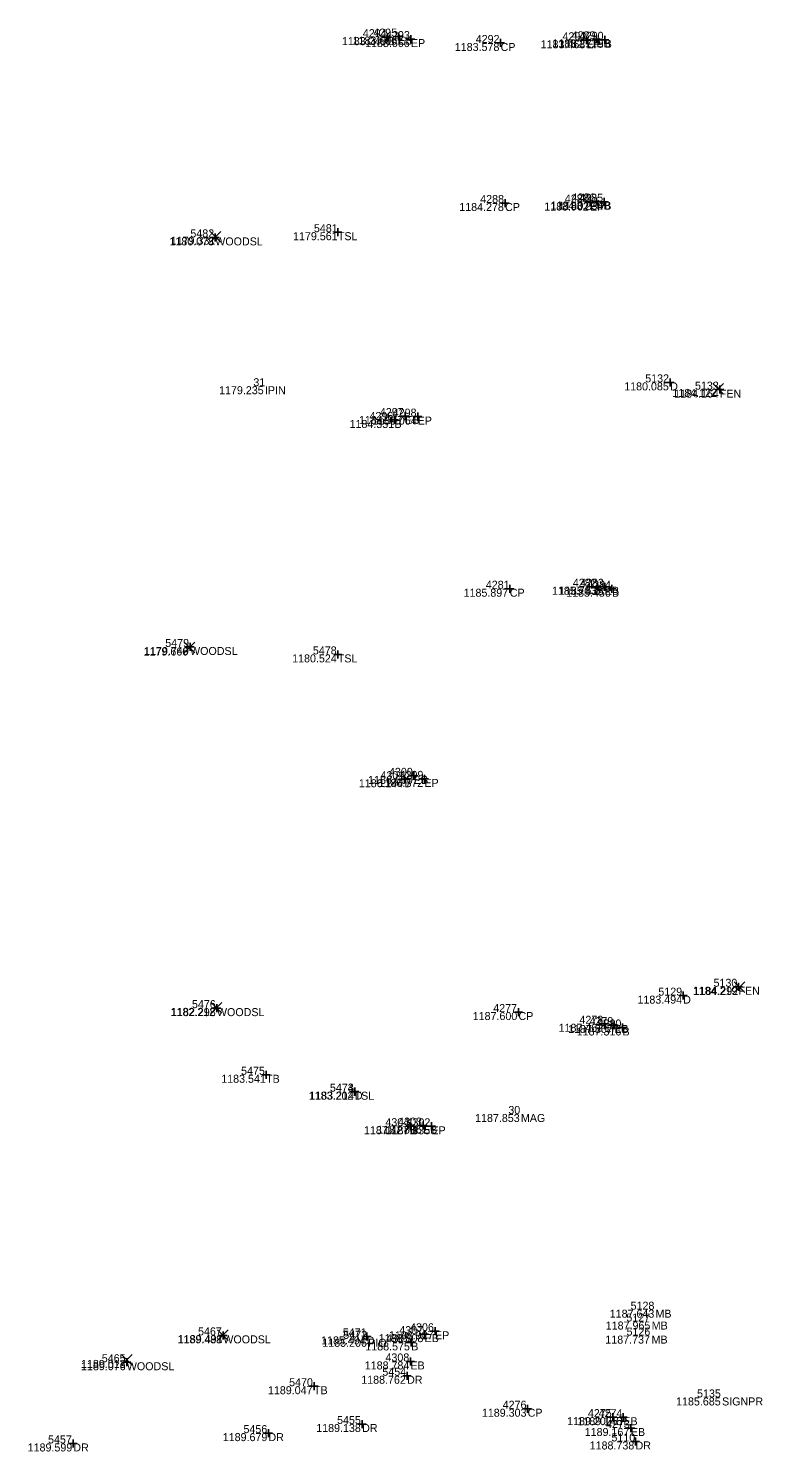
# Model space of a CAD drawing. Extents: x 2044997 to 2050342, y 455233 to 458054.
# Drawn here: x 2047553.1 to 2047644.9, y 457876.5 to 458054.4 of the extents above; entities that cross this region are included whole.
import ezdxf

# ---------------------------------------------------------------- set-up
doc = ezdxf.new("R2010")
doc.units = 0
for name, color, linetype in [('SV_X_Random_Point', 7, 'Continuous'), ('SV_X_Shot_Marker', 7, 'Continuous'), ('SV_X_Text_Comment', 7, 'Continuous'), ('SV_X_Text_Elevation', 7, 'Continuous'), ('SV_X_Text_Name', 7, 'Continuous')]:
    doc.layers.add(name, color=color, linetype=linetype)

msp = doc.modelspace()

# ---------------------------------------------------------------- linework, layer by layer
at = {"layer": 'SV_X_Random_Point'}
for p, q in [((2047575.85, 458027.66), (2047577.18, 458028.99)), ((2047575.85, 458028.99), (2047577.18, 458027.66)), ((2047638.7, 458008.64), (2047640.03, 458009.97)), ((2047638.7, 458009.97), (2047640.03, 458008.64)), ((2047572.58, 457976.32), (2047573.91, 457977.65)), ((2047572.58, 457977.65), (2047573.91, 457976.32)), ((2047641.36, 457933.88), (2047642.69, 457935.21)), ((2047641.36, 457935.21), (2047642.69, 457933.88)), ((2047575.95, 457931.27), (2047577.29, 457932.61)), ((2047575.95, 457932.61), (2047577.29, 457931.27)), ((2047576.74, 457890.38), (2047578.08, 457891.72)), ((2047576.74, 457891.72), (2047578.08, 457890.38)), ((2047564.73, 457887.27), (2047566.07, 457888.61)), ((2047564.73, 457888.61), (2047566.07, 457887.27))]:
    msp.add_line(p, q, dxfattribs=at)
at = {"layer": 'SV_X_Shot_Marker'}
for p, q in [((2047597.52, 458053.27), (2047598.52, 458053.27)), ((2047598.02, 458053.77), (2047598.02, 458052.77)), ((2047598.02, 458053.27), (2047598.02, 458053.27)), ((2047598.87, 458053.34), (2047599.87, 458053.34)), ((2047599.37, 458053.84), (2047599.37, 458052.84)), ((2047599.37, 458053.34), (2047599.37, 458053.34)), ((2047600.44, 458053.03), (2047601.44, 458053.03)), ((2047600.94, 458053.53), (2047600.94, 458052.53)), ((2047600.94, 458053.03), (2047600.94, 458053.03)), ((2047611.66, 458052.54), (2047612.66, 458052.54)), ((2047612.16, 458053.04), (2047612.16, 458052.04)), ((2047612.16, 458052.54), (2047612.16, 458052.54)), ((2047622.4, 458052.88), (2047623.4, 458052.88)), ((2047622.9, 458053.38), (2047622.9, 458052.38)), ((2047622.9, 458052.88), (2047622.9, 458052.88)), ((2047623.65, 458053), (2047624.65, 458053)), ((2047624.15, 458053.5), (2047624.15, 458052.5)), ((2047624.15, 458053), (2047624.15, 458053)), ((2047624.68, 458052.94), (2047625.68, 458052.94)), ((2047625.18, 458053.44), (2047625.18, 458052.44)), ((2047625.18, 458052.94), (2047625.18, 458052.94)), ((2047612.72, 458033.04), (2047612.72, 458032.04)), ((2047623.35, 458033.1), (2047623.35, 458032.1)), ((2047624.15, 458033.23), (2047624.15, 458032.23)), ((2047625.13, 458033.2), (2047625.13, 458032.2)), ((2047612.22, 458032.54), (2047613.22, 458032.54)), ((2047612.72, 458032.54), (2047612.72, 458032.54)), ((2047622.85, 458032.6), (2047623.85, 458032.6)), ((2047623.35, 458032.6), (2047623.35, 458032.6)), ((2047623.65, 458032.73), (2047624.65, 458032.73)), ((2047624.15, 458032.73), (2047624.15, 458032.73)), ((2047624.63, 458032.7), (2047625.63, 458032.7)), ((2047625.13, 458032.7), (2047625.13, 458032.7)), ((2047591.81, 458029.39), (2047591.81, 458028.39)), ((2047575.97, 458028.24), (2047576.97, 458028.24)), ((2047576.47, 458028.74), (2047576.47, 458027.74)), ((2047576.47, 458028.24), (2047576.47, 458028.24)), ((2047591.31, 458028.89), (2047592.31, 458028.89)), ((2047591.81, 458028.89), (2047591.81, 458028.89)), ((2047632.87, 458010.12), (2047633.87, 458010.12)), ((2047633.37, 458010.62), (2047633.37, 458009.62)), ((2047633.37, 458010.12), (2047633.37, 458010.12)), ((2047639.58, 458009.71), (2047639.58, 458008.71)), ((2047639.08, 458009.21), (2047640.08, 458009.21)), ((2047639.58, 458009.21), (2047639.58, 458009.21)), ((2047600.22, 458006.41), (2047600.22, 458005.41)), ((2047601.79, 458006.34), (2047601.79, 458005.34)), ((2047598.38, 458005.42), (2047599.38, 458005.42)), ((2047598.88, 458005.92), (2047598.88, 458004.92)), ((2047598.88, 458005.42), (2047598.88, 458005.42)), ((2047599.72, 458005.91), (2047600.72, 458005.91)), ((2047600.22, 458005.91), (2047600.22, 458005.91)), ((2047601.29, 458005.84), (2047602.29, 458005.84)), ((2047601.79, 458005.84), (2047601.79, 458005.84)), ((2047613.31, 457984.83), (2047613.31, 457983.83)), ((2047624.3, 457985.08), (2047624.3, 457984.08)), ((2047625.21, 457985.07), (2047625.21, 457984.07)), ((2047626.09, 457984.83), (2047626.09, 457983.83)), ((2047612.81, 457984.33), (2047613.81, 457984.33)), ((2047613.31, 457984.33), (2047613.31, 457984.33)), ((2047623.8, 457984.58), (2047624.8, 457984.58)), ((2047624.3, 457984.58), (2047624.3, 457984.58)), ((2047624.71, 457984.57), (2047625.71, 457984.57)), ((2047625.21, 457984.57), (2047625.21, 457984.57)), ((2047625.59, 457984.33), (2047626.59, 457984.33)), ((2047626.09, 457984.33), (2047626.09, 457984.33)), ((2047572.82, 457977.05), (2047573.82, 457977.05)), ((2047573.32, 457977.55), (2047573.32, 457976.55)), ((2047573.32, 457977.05), (2047573.32, 457977.05)), ((2047591.3, 457976.12), (2047592.3, 457976.12)), ((2047591.8, 457976.62), (2047591.8, 457975.62)), ((2047591.8, 457976.12), (2047591.8, 457976.12)), ((2047599.63, 457960.52), (2047600.63, 457960.52)), ((2047600.13, 457961.02), (2047600.13, 457960.02)), ((2047600.13, 457960.52), (2047600.13, 457960.52)), ((2047600.82, 457960.94), (2047601.82, 457960.94)), ((2047601.32, 457961.44), (2047601.32, 457960.44)), ((2047601.32, 457960.94), (2047601.32, 457960.94)), ((2047602.13, 457960.56), (2047603.13, 457960.56)), ((2047602.63, 457961.06), (2047602.63, 457960.06)), ((2047602.63, 457960.56), (2047602.63, 457960.56)), ((2047641.91, 457935.08), (2047641.91, 457934.08)), ((2047634.49, 457933.47), (2047635.49, 457933.47)), ((2047634.99, 457933.97), (2047634.99, 457932.97)), ((2047634.99, 457933.47), (2047634.99, 457933.47)), ((2047641.41, 457934.58), (2047642.41, 457934.58)), ((2047641.91, 457934.58), (2047641.91, 457934.58)), ((2047576.18, 457931.91), (2047577.18, 457931.91)), ((2047576.68, 457932.41), (2047576.68, 457931.41)), ((2047576.68, 457931.91), (2047576.68, 457931.91)), ((2047613.9, 457931.42), (2047614.9, 457931.42)), ((2047614.4, 457931.92), (2047614.4, 457930.92)), ((2047614.4, 457931.42), (2047614.4, 457931.42)), ((2047624.64, 457929.95), (2047625.64, 457929.95)), ((2047625.14, 457930.45), (2047625.14, 457929.45)), ((2047625.14, 457929.95), (2047625.14, 457929.95)), ((2047625.88, 457929.8), (2047626.88, 457929.8)), ((2047626.38, 457930.3), (2047626.38, 457929.3)), ((2047626.38, 457929.8), (2047626.38, 457929.8)), ((2047627.41, 457929.99), (2047627.41, 457928.99)), ((2047626.91, 457929.49), (2047627.91, 457929.49)), ((2047627.41, 457929.49), (2047627.41, 457929.49)), ((2047582.33, 457923.58), (2047583.33, 457923.58)), ((2047582.83, 457924.08), (2047582.83, 457923.08)), ((2047582.83, 457923.58), (2047582.83, 457923.58)), ((2047593.4, 457921.46), (2047594.4, 457921.46)), ((2047593.43, 457921.48), (2047594.43, 457921.48)), ((2047593.9, 457921.96), (2047593.9, 457920.96)), ((2047593.9, 457921.46), (2047593.9, 457921.46)), ((2047593.93, 457921.98), (2047593.93, 457920.98)), ((2047593.93, 457921.48), (2047593.93, 457921.48)), ((2047600.34, 457917.15), (2047601.34, 457917.15)), ((2047600.84, 457917.65), (2047600.84, 457916.65)), ((2047600.84, 457917.15), (2047600.84, 457917.15)), ((2047601.96, 457917.23), (2047602.96, 457917.23)), ((2047602.46, 457917.73), (2047602.46, 457916.73)), ((2047602.46, 457917.23), (2047602.46, 457917.23)), ((2047603.01, 457917.14), (2047604.01, 457917.14)), ((2047603.51, 457917.64), (2047603.51, 457916.64)), ((2047603.51, 457917.14), (2047603.51, 457917.14)), ((2047576.98, 457891.01), (2047577.98, 457891.01)), ((2047577.48, 457891.51), (2047577.48, 457890.51)), ((2047577.48, 457891.01), (2047577.48, 457891.01)), ((2047594.91, 457890.88), (2047595.91, 457890.88)), ((2047595.41, 457891.38), (2047595.41, 457890.38)), ((2047595.41, 457890.88), (2047595.41, 457890.88)), ((2047600.98, 457890.63), (2047600.98, 457889.63)), ((2047602.15, 457891.16), (2047603.15, 457891.16)), ((2047602.65, 457891.66), (2047602.65, 457890.66)), ((2047602.65, 457891.16), (2047602.65, 457891.16)), ((2047603.46, 457891.52), (2047604.46, 457891.52)), ((2047603.96, 457892.02), (2047603.96, 457891.02)), ((2047603.96, 457891.52), (2047603.96, 457891.52)), ((2047600.48, 457890.13), (2047601.48, 457890.13)), ((2047600.98, 457890.13), (2047600.98, 457890.13)), ((2047564.91, 457887.65), (2047565.91, 457887.65)), ((2047565.41, 457888.15), (2047565.41, 457887.15)), ((2047565.41, 457887.65), (2047565.41, 457887.65)), ((2047600.38, 457887.75), (2047601.38, 457887.75)), ((2047600.88, 457888.25), (2047600.88, 457887.25)), ((2047600.88, 457887.75), (2047600.88, 457887.75)), ((2047588.83, 457885.15), (2047588.83, 457884.15)), ((2047599.96, 457885.96), (2047600.96, 457885.96)), ((2047600.46, 457886.46), (2047600.46, 457885.46)), ((2047600.46, 457885.96), (2047600.46, 457885.96)), ((2047588.33, 457884.65), (2047589.33, 457884.65)), ((2047588.83, 457884.65), (2047588.83, 457884.65)), ((2047615.04, 457881.84), (2047616.04, 457881.84)), ((2047615.54, 457882.34), (2047615.54, 457881.34)), ((2047615.54, 457881.84), (2047615.54, 457881.84)), ((2047594.34, 457879.93), (2047595.34, 457879.93)), ((2047594.84, 457880.43), (2047594.84, 457879.43)), ((2047594.84, 457879.93), (2047594.84, 457879.93)), ((2047625.71, 457880.79), (2047626.71, 457880.79)), ((2047626.21, 457881.29), (2047626.21, 457880.29)), ((2047626.21, 457880.79), (2047626.21, 457880.79)), ((2047627.01, 457880.78), (2047628.01, 457880.78)), ((2047627.51, 457881.28), (2047627.51, 457880.28)), ((2047627.51, 457880.78), (2047627.51, 457880.78)), ((2047628.45, 457879.93), (2047628.45, 457878.93)), ((2047558.72, 457878), (2047558.72, 457877)), ((2047582.62, 457878.79), (2047583.62, 457878.79)), ((2047583.12, 457879.29), (2047583.12, 457878.29)), ((2047583.12, 457878.79), (2047583.12, 457878.79)), ((2047627.95, 457879.43), (2047628.95, 457879.43)), ((2047628.45, 457879.43), (2047628.45, 457879.43)), ((2047629.04, 457878.25), (2047629.04, 457877.25)), ((2047558.22, 457877.5), (2047559.22, 457877.5)), ((2047558.72, 457877.5), (2047558.72, 457877.5)), ((2047628.54, 457877.75), (2047629.54, 457877.75)), ((2047629.04, 457877.75), (2047629.04, 457877.75))]:
    msp.add_line(p, q, dxfattribs=at)

# ---------------------------------------------------------------- texts
at = {"layer": 'SV_X_Text_Comment'}
for s, p in [('B', (2047598.02, 458052.27)), ('EB', (2047599.37, 458052.34)), ('EP', (2047600.94, 458052.03)), ('CP', (2047612.16, 458051.54)), ('EP', (2047622.9, 458051.88)), ('EB', (2047624.15, 458052)), ('B', (2047625.18, 458051.94)), ('CP', (2047612.72, 458031.54)), ('EP', (2047623.35, 458031.6)), ('EB', (2047624.15, 458031.73)), ('B', (2047625.13, 458031.7)), ('WOODSL', (2047576.47, 458027.24)), ('TSL', (2047591.81, 458027.89)), ('IPIN', (2047582.69, 458008.64)), ('D', (2047633.37, 458009.12)), ('FEN', (2047639.58, 458008.21)), ('B', (2047598.88, 458004.42)), ('EB', (2047600.22, 458004.91)), ('EP', (2047601.79, 458004.84)), ('CP', (2047613.31, 457983.33)), ('EP', (2047624.3, 457983.58)), ('EB', (2047625.21, 457983.57)), ('B', (2047626.09, 457983.33)), ('WOODSL', (2047573.32, 457976.05)), ('TSL', (2047591.8, 457975.12)), ('B', (2047600.13, 457959.52)), ('EB', (2047601.32, 457959.94)), ('EP', (2047602.63, 457959.56)), ('D', (2047634.99, 457932.47)), ('FEN', (2047641.91, 457933.58)), ('WOODSL', (2047576.68, 457930.91)), ('CP', (2047614.4, 457930.42)), ('EP', (2047625.14, 457928.95)), ('EB', (2047626.38, 457928.8)), ('B', (2047627.41, 457928.49)), ('TB', (2047582.83, 457922.58)), ('TSL', (2047593.9, 457920.46)), ('D', (2047593.93, 457920.48)), ('B', (2047600.84, 457916.15)), ('EB', (2047602.46, 457916.23)), ('EP', (2047603.51, 457916.14)), ('MAG', (2047614.7, 457917.68)), ('MB', (2047631.53, 457893.22)), ('MB', (2047631.06, 457891.74)), ('WOODSL', (2047577.48, 457890.01)), ('D', (2047595.41, 457889.88)), ('PIO', (2047595.6, 457889.58)), ('EB', (2047602.65, 457890.16)), ('EP', (2047603.96, 457890.52)), ('MB', (2047631.04, 457889.98)), ('B', (2047600.98, 457889.13)), ('WOODSL', (2047565.41, 457886.65)), ('EB', (2047600.88, 457886.75)), ('DR', (2047600.46, 457884.96)), ('TB', (2047588.83, 457883.65)), ('CP', (2047615.54, 457880.84)), ('SIGNPR', (2047639.86, 457882.25)), ('DR', (2047594.84, 457878.93)), ('EP', (2047626.21, 457879.79)), ('EB', (2047627.51, 457879.78)), ('DR', (2047583.12, 457877.79)), ('EB', (2047628.45, 457878.43)), ('DR', (2047558.72, 457876.5)), ('DR', (2047629.04, 457876.75))]:
    msp.add_text(s, height=1, dxfattribs=at).set_placement(p)
at = {"layer": 'SV_X_Text_Elevation'}
for s, p in [('1183.249', (2047592.31, 458052.27)), ('1183.606', (2047593.64, 458052.34)), ('1183.666', (2047595.21, 458052.03)), ('1183.578', (2047606.43, 458051.54)), ('1183.463', (2047617.17, 458051.88)), ('1183.211', (2047618.64, 458052)), ('1182.779', (2047619.47, 458051.94)), ('1184.072', (2047618.42, 458031.73)), ('1184.278', (2047606.99, 458031.54)), ('1183.902', (2047617.62, 458031.6)), ('1183.234', (2047619.43, 458031.7)), ('1180.078', (2047570.74, 458027.24)), ('1179.331', (2047570.9, 458027.33)), ('1179.561', (2047586.2, 458027.89)), ('1179.235', (2047576.95, 458008.64)), ('1180.085', (2047627.62, 458009.12)), ('1184.122', (2047633.64, 458008.3)), ('1184.164', (2047633.87, 458008.21)), ('1184.551', (2047593.27, 458004.42)), ('1184.947', (2047594.44, 458004.91)), ('1185.064', (2047596.08, 458004.84)), ('1185.897', (2047607.53, 457983.33)), ('1185.733', (2047618.58, 457983.58)), ('1185.635', (2047619.46, 457983.57)), ('1185.456', (2047620.36, 457983.33)), ('1179.666', (2047567.51, 457975.98)), ('1179.740', (2047567.58, 457976.05)), ('1180.524', (2047586.09, 457975.12)), ('1186.144', (2047594.43, 457959.52)), ('1186.600', (2047595.59, 457959.94)), ('1186.772', (2047596.9, 457959.56)), ('1183.494', (2047629.28, 457932.47)), ('1184.219', (2047636.2, 457933.58)), ('1184.292', (2047636.29, 457933.55)), ('1182.212', (2047570.89, 457930.94)), ('1182.298', (2047570.95, 457930.91)), ('1187.600', (2047608.67, 457930.42)), ('1187.462', (2047619.41, 457928.95)), ('1187.367', (2047620.6, 457928.8)), ('1187.316', (2047621.68, 457928.49)), ('1183.541', (2047577.22, 457922.58)), ('1183.202', (2047588.17, 457920.46)), ('1183.214', (2047588.23, 457920.48)), ('1187.427', (2047595.07, 457916.15)), ('1187.886', (2047596.72, 457916.23)), ('1187.835', (2047597.77, 457916.14)), ('1187.853', (2047608.97, 457917.68)), ('1187.643', (2047625.81, 457893.22)), ('1187.965', (2047625.31, 457891.74)), ('1189.488', (2047571.75, 457890.01)), ('1189.491', (2047571.8, 457890.05)), ('1185.494', (2047589.71, 457889.88)), ('1185.206', (2047589.86, 457889.58)), ('1188.808', (2047596.92, 457890.16)), ('1188.927', (2047598.19, 457890.52)), ('1187.737', (2047625.26, 457889.98)), ('1188.575', (2047595.24, 457889.13)), ('1189.013', (2047559.68, 457886.94)), ('1189.076', (2047559.68, 457886.65)), ('1188.784', (2047595.17, 457886.75)), ('1188.762', (2047594.73, 457884.96)), ('1189.047', (2047583.06, 457883.65)), ('1189.303', (2047609.82, 457880.84)), ('1185.685', (2047634.11, 457882.25)), ('1189.138', (2047589.1, 457878.93)), ('1189.200', (2047620.48, 457879.79)), ('1189.146', (2047621.77, 457879.78)), ('1189.679', (2047577.41, 457877.79)), ('1189.167', (2047622.68, 457878.43)), ('1189.599', (2047553.01, 457876.5)), ('1188.738', (2047623.3, 457876.75))]:
    msp.add_text(s, height=1, dxfattribs=at).set_placement(p)
at = {"layer": 'SV_X_Text_Name'}
for s, p in [('4294', (2047594.93, 458053.27)), ('4295', (2047596.24, 458053.34)), ('4293', (2047597.84, 458053.03)), ('4292', (2047609.05, 458052.54)), ('4291', (2047619.9, 458052.88)), ('4289', (2047621.05, 458053)), ('4290', (2047622.06, 458052.94)), ('4288', (2047609.61, 458032.54)), ('4287', (2047620.19, 458032.6)), ('4286', (2047621.03, 458032.73)), ('4285', (2047622, 458032.7)), ('5482', (2047573.36, 458028.24)), ('5481', (2047588.81, 458028.89)), ('31', (2047581.24, 458009.64)), ('5132', (2047630.25, 458010.12)), ('5133', (2047636.47, 458009.21)), ('4296', (2047595.76, 458005.42)), ('4297', (2047597.06, 458005.91)), ('4298', (2047598.67, 458005.84)), ('4281', (2047610.31, 457984.33)), ('4282', (2047621.19, 457984.58)), ('4283', (2047622.1, 457984.57)), ('4284', (2047623, 457984.33)), ('5479', (2047570.22, 457977.05)), ('5478', (2047588.68, 457976.12)), ('4300', (2047598.2, 457960.94)), ('4301', (2047597.14, 457960.52)), ('4299', (2047599.53, 457960.56)), ('5130', (2047638.79, 457934.58)), ('5129', (2047631.89, 457933.47)), ('5476', (2047573.56, 457931.91)), ('4277', (2047611.24, 457931.42)), ('4278', (2047622.02, 457929.95)), ('4279', (2047623.28, 457929.8)), ('4280', (2047624.29, 457929.49)), ('5475', (2047579.7, 457923.58)), ('5474', (2047590.81, 457921.46)), ('5473', (2047590.82, 457921.48)), ('30', (2047613.13, 457918.68)), ('4304', (2047597.75, 457917.15)), ('4303', (2047599.35, 457917.23)), ('4302', (2047600.4, 457917.14)), ('5128', (2047628.42, 457894.22)), ('4306', (2047600.84, 457891.52)), ('5127', (2047627.89, 457892.74)), ('5467', (2047574.32, 457891.01)), ('5471', (2047592.42, 457890.88)), ('5472', (2047592.49, 457890.58)), ('4305', (2047597.85, 457890.13)), ('4307', (2047599.49, 457891.16)), ('5126', (2047627.91, 457890.98)), ('4308', (2047597.76, 457887.75)), ('5465', (2047562.28, 457887.65)), ('5454', (2047597.37, 457885.96)), ('5470', (2047585.71, 457884.65)), ('5135', (2047636.73, 457883.25)), ('4276', (2047612.42, 457881.84)), ('4275', (2047623.08, 457880.79)), ('4274', (2047624.42, 457880.78)), ('5456', (2047580, 457878.79)), ('5455', (2047591.71, 457879.93)), ('4273', (2047625.34, 457879.43)), ('5457', (2047555.56, 457877.5)), ('5110', (2047626.02, 457877.75))]:
    msp.add_text(s, height=1, dxfattribs=at).set_placement(p)

doc.saveas('drawing.dxf')
